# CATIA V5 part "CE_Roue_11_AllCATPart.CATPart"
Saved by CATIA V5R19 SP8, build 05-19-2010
Part number: CE14_Roue_11_AllCATPart
Bounding box of the stored display mesh (mm): x -96.759 to -71.769, y 118.747 to 140.559, z 118.799 to 134.814
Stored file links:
  D:\Documents\1_Travail\1 - ac-limoges.fr\ac-limoges.fr\Emmanuel Maynard - STI2D_Turgot\2 -2I2D\1_SEQUENCE_ Tapis_de_course\3- Spécificités\Spé_ITEC\3-Pente\Tapis_TC520B_Pente\CE_Roue_11_AllCATPart.CATPart
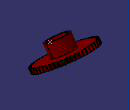
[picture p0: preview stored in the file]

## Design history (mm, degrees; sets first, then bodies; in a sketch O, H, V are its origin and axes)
AxisSystem1: origin (0, 0, 0), X (1, 0, 0), Y (0, 1, 0), Z (0, 0, 1)
Body1 (main body)
  Sketch1 on face of Solid1, origin (0, -21.6704, 31.9965), H (1, 0, 0), V (0, 0.828, 0.5608)
    point P1 (-80.3695, 179.2739)
    reference projected circle E1 centre (-84.2639, 178.3609) radius 4 from edge [face of Solid1 | face of Solid1]
    coincidence: P1 E1
Body2 "CE_Roue_11.1\\Corps principal"
  Solid1: solid without history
